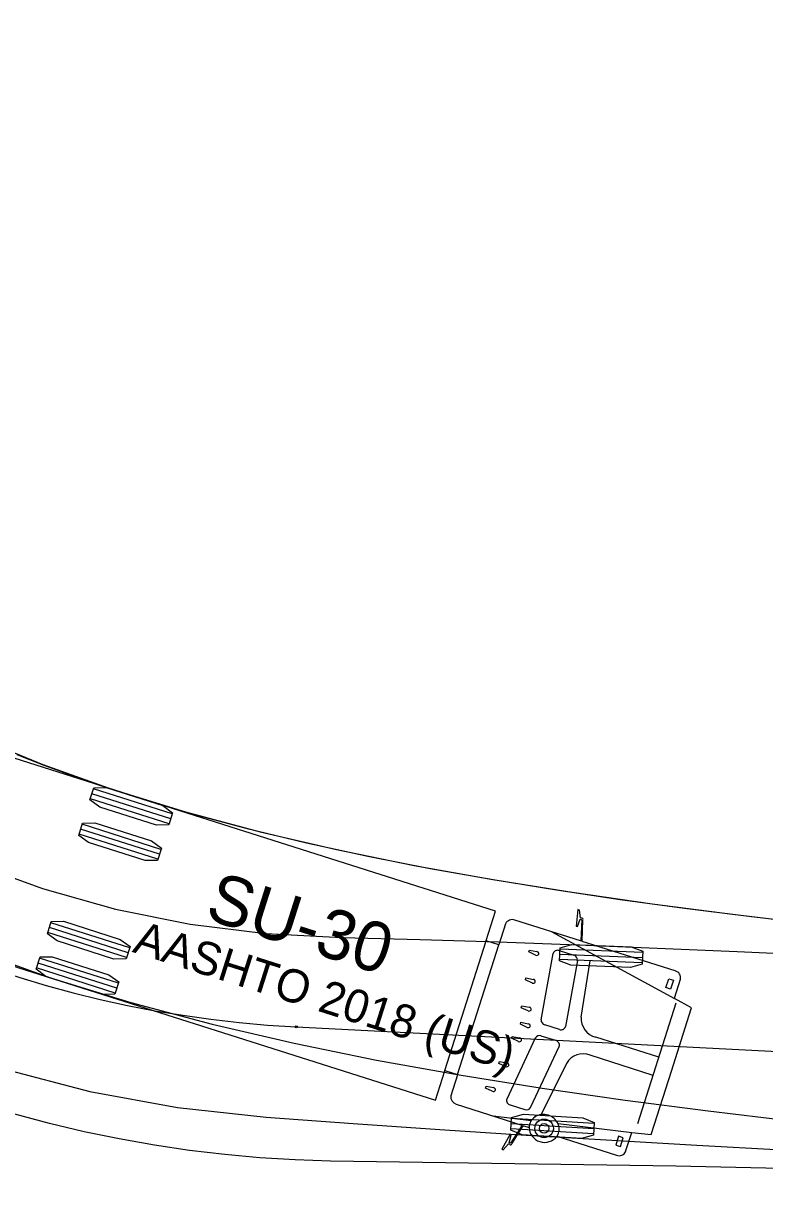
# Model space of a CAD drawing. Extents: x 260275 to 261282, y 610916 to 614143.
# Drawn here: x 261055.33 to 261085.23, y 611607.94 to 611654.93 of the extents above; entities that cross this region are included whole.
import ezdxf

# ---------------------------------------------------------------- set-up
doc = ezdxf.new("R2010")
doc.units = 0
doc.layers.add('UT_X_Water_Cells', color=7, linetype='Continuous')

msp = doc.modelspace()

# ---------------------------------------------------------------- linework, layer by layer
at = {"layer": 'UT_X_Water_Cells'}
for p, q in [((261061.276, 611622.828), (261058.1, 611623.838)), ((261061.339, 611623.027), (261058.163, 611624.037)), ((261061.213, 611622.63), (261058.036, 611623.64)), ((261060.885, 611621.597), (261057.708, 611622.607)), ((261060.758, 611621.2), (261057.582, 611622.21)), ((261060.821, 611621.399), (261057.645, 611622.409)), ((261059.496, 611617.229), (261056.319, 611618.24)), ((261059.559, 611617.428), (261056.382, 611618.438)), ((261059.622, 611617.626), (261056.445, 611618.637)), ((261076.646, 611618.273), (261081.591, 611615.583)), ((261072.337, 611612.669), (261074.002, 611617.903)), ((261072.844, 611612.508), (261074.508, 611617.741)), ((261075.719, 611617.457), (261075.744, 611617.535)), ((261075.994, 611617.331), (261075.719, 611617.457)), ((261075.744, 611617.535), (261076.04, 611617.479)), ((261076.219, 611614.725), (261076.7, 611617.399)), ((261076.948, 611617.511), (261077.535, 611617.324)), ((261080.303, 611617.224), (261076.972, 611617.358)), ((261080.311, 611617.432), (261076.981, 611617.567)), ((261059.041, 611615.8), (261055.864, 611616.81)), ((261059.104, 611615.998), (261055.928, 611617.009)), ((261059.167, 611616.197), (261055.991, 611617.207)), ((261080.295, 611617.016), (261076.964, 611617.15)), ((261077.682, 611617.118), (261077.201, 611614.444)), ((261077.834, 611614.832), (261078.192, 611617.094)), ((261075.581, 611616.328), (261075.606, 611616.407)), ((261075.869, 611616.2), (261075.581, 611616.328)), ((261075.606, 611616.407), (261075.916, 611616.347)), ((261081.251, 611616.017), (261081.365, 611616.378)), ((261081.365, 611616.378), (261081.55, 611616.319)), ((261081.436, 611615.958), (261081.251, 611616.017)), ((261081.55, 611616.319), (261081.436, 611615.958)), ((261080.115, 611610.538), (261081.663, 611615.403)), ((261075.416, 611615.208), (261075.441, 611615.287)), ((261075.691, 611615.083), (261075.416, 611615.208)), ((261075.441, 611615.287), (261075.738, 611615.23)), ((261075.38, 611614.539), (261075.405, 611614.618)), ((261075.655, 611614.414), (261075.38, 611614.539)), ((261075.405, 611614.618), (261075.701, 611614.561)), ((261076.953, 611614.332), (261076.365, 611614.519)), ((261066.343, 611614.434), (261269.731, 611604.069)), ((261075.983, 611613.982), (261074.831, 611611.521)), ((261075.023, 611613.973), (261075.048, 611614.051)), ((261075.298, 611613.848), (261075.023, 611613.973)), ((261075.048, 611614.051), (261075.345, 611613.995)), ((261076.809, 611613.879), (261076.221, 611614.066)), ((261080.965, 611613.208), (261078.422, 611614.017)), ((261075.795, 611611.183), (261076.946, 611613.644)), ((261074.511, 611612.963), (261074.536, 611613.042)), ((261074.536, 611613.042), (261074.832, 611612.985)), ((261080.733, 611612.479), (261078.19, 611613.287)), ((261074.786, 611612.838), (261074.511, 611612.963)), ((261077.24, 611612.961), (261076.219, 611610.898)), ((261073.972, 611611.962), (261073.997, 611612.041)), ((261074.246, 611611.837), (261073.972, 611611.962)), ((261073.997, 611612.041), (261074.293, 611611.984)), ((261074.969, 611611.287), (261075.556, 611611.1)), ((261074.282, 611610.84), (261075.82, 611610.658)), ((261078.353, 611610.53), (261075.025, 611610.733)), ((261078.327, 611610.114), (261075, 611610.317)), ((261078.34, 611610.322), (261075.013, 611610.525)), ((261076.898, 611610.53), (261079.872, 611610.179)), ((261076.857, 611610.02), (261079.261, 611609.256)), ((261079.344, 611610.021), (261079.229, 611609.66)), ((261079.529, 611609.962), (261079.344, 611610.021)), ((261079.414, 611609.601), (261079.529, 611609.962)), ((261079.229, 611609.66), (261079.414, 611609.601))]:
    msp.add_line(p, q, dxfattribs=at)
for points in [[(261053.428, 611626.129), (261056.118, 611625.015), (261058.944, 611624.011), (261061.876, 611623.111), (261064.891, 611622.308), (261067.97, 611621.591), (261071.1, 611620.951), (261074.269, 611620.378), (261077.468, 611619.864), (261080.693, 611619.4), (261083.936, 611618.979), (261087.195, 611618.596)], [(261074.781, 611618.598), (261074.509, 611617.744), (261074.505, 611617.743), (261074.003, 611617.902), (261074.005, 611617.913), (261074.382, 611619.098), (261054.096, 611625.549), (261052.884, 611621.737), (261051.672, 611617.925), (261071.957, 611611.474), (261072.334, 611612.658), (261072.338, 611612.669), (261072.84, 611612.509), (261072.843, 611612.505), (261072.571, 611611.651)], [(261055.07, 611625.429), (261056.161, 611624.999), (261057.273, 611624.586), (261058.405, 611624.191), (261059.555, 611623.813), (261061.903, 611623.104), (261064.305, 611622.456), (261066.75, 611621.864), (261069.232, 611621.323), (261071.743, 611620.829), (261074.279, 611620.377), (261076.835, 611619.961), (261079.407, 611619.579), (261081.994, 611619.226), (261084.592, 611618.899), (261087.2, 611618.596)], [(261053.21, 611621.06), (261056.099, 611620.012), (261059.056, 611619.184), (261062.066, 611618.578), (261065.112, 611618.198), (261068.183, 611618.045), (261071.333, 611617.966), (261074.504, 611617.865), (261077.694, 611617.746), (261080.902, 611617.614), (261084.127, 611617.473), (261087.366, 611617.325)], [(261077.847, 611618.814), (261077.802, 611618.829), (261077.801, 611618.829), (261077.765, 611619.15), (261077.703, 611619.17), (261077.703, 611619.167), (261077.637, 611618.5), (261077.637, 611618.497), (261077.69, 611618.48), (261077.691, 611618.482), (261077.795, 611618.782), (261077.796, 611618.782), (261077.838, 611618.768)], [(261077.854, 611618.751), (261077.854, 611618.751), (261077.815, 611617.906), (261077.802, 611617.905), (261075.159, 611618.746)], [(261081.625, 611616.689), (261077.877, 611617.881), (261077.867, 611617.891), (261077.904, 611618.752), (261077.904, 611618.753)], [(261053.236, 611617.552), (261056.422, 611616.419), (261059.665, 611615.423), (261062.948, 611614.548), (261066.256, 611613.777), (261069.582, 611613.096), (261072.918, 611612.493), (261076.261, 611611.956), (261079.606, 611611.474), (261082.953, 611611.04), (261086.299, 611610.647)], [(261079.627, 611609.406), (261079.871, 611610.175), (261079.877, 611610.178), (261080.657, 611610.086), (261080.672, 611610.126), (261081.473, 611612.645), (261082.274, 611615.164), (261082.285, 611615.205), (261081.595, 611615.58), (261081.592, 611615.586), (261081.837, 611616.356)], [(261054.534, 611612.738), (261058.013, 611611.83), (261061.551, 611611.18), (261065.122, 611610.792), (261068.642, 611610.531), (261072.138, 611610.292), (261075.613, 611610.071), (261079.067, 611609.863), (261082.504, 611609.665), (261085.925, 611609.474)], [(261072.795, 611611.312), (261075.438, 611610.472), (261075.448, 611610.463), (261074.992, 611609.751), (261074.991, 611609.751)], [(261087.099, 611608.697), (261081.645, 611608.809), (261067.722, 611609.015), (261066.3, 611609.063), (261064.878, 611609.151), (261063.456, 611609.28), (261062.036, 611609.449), (261060.618, 611609.659), (261059.203, 611609.911), (261057.792, 611610.204), (261056.385, 611610.538), (261054.985, 611610.914)], [(261075.031, 611609.72), (261075.032, 611609.721), (261075.499, 611610.445), (261075.513, 611610.448), (261075.73, 611610.379)], [(261074.969, 611609.746), (261074.926, 611609.759), (261074.926, 611609.76), (261075.014, 611610.065), (261075.015, 611610.067), (261074.962, 611610.084), (261074.96, 611610.082), (261074.628, 611609.499), (261074.627, 611609.496), (261074.689, 611609.476), (261074.904, 611609.718), (261074.904, 611609.718), (261074.95, 611609.704)]]:
    msp.add_lwpolyline(points, dxfattribs=at)
for points in [[(261061.355, 611623.076), (261061.197, 611622.58), (261060.705, 611622.572), (261058.418, 611623.3), (261058.021, 611623.591), (261058.178, 611624.086), (261058.67, 611624.094), (261060.958, 611623.367)], [(261060.9, 611621.646), (261060.743, 611621.151), (261060.25, 611621.143), (261057.963, 611621.87), (261057.566, 611622.161), (261057.724, 611622.657), (261058.216, 611622.664), (261060.503, 611621.937)], [(261059.638, 611617.676), (261059.48, 611617.18), (261058.988, 611617.172), (261056.701, 611617.9), (261056.303, 611618.19), (261056.461, 611618.686), (261056.953, 611618.694), (261059.24, 611617.966)], [(261080.314, 611617.484), (261080.293, 611616.964), (261079.82, 611616.827), (261077.422, 611616.923), (261076.962, 611617.099), (261076.983, 611617.618), (261077.455, 611617.756), (261079.854, 611617.659)], [(261059.183, 611616.246), (261059.025, 611615.751), (261058.533, 611615.743), (261056.246, 611616.47), (261055.849, 611616.761), (261056.006, 611617.256), (261056.499, 611617.264), (261058.786, 611616.537)], [(261078.356, 611610.582), (261078.324, 611610.063), (261077.849, 611609.935), (261075.453, 611610.081), (261074.997, 611610.265), (261075.028, 611610.784), (261075.504, 611610.912), (261077.899, 611610.767)]]:
    msp.add_lwpolyline(points, close=True, dxfattribs=at)
for centre, radius in [((261066.343, 611614.434), 0.0417), ((261066.343, 611614.434), 0.0417), ((261076.338, 611610.338), 0.374), ((261076.338, 611610.338), 0.193)]:
    msp.add_circle(centre, radius, dxfattribs=at)
for centre, radius, start, end in [((261068.634, 611659.376), 45, 177.1255, 267.0825), ((261052.872, 611624.635), 42, 177.1255, 293.7992), ((261075.061, 611618.438), 0.323, 72.3587, 150.2071), ((261077.876, 611618.788), 0.0434, 207.7724, 238.4451), ((261077.874, 611618.783), 0.0418, 314.8506, 131.8655), ((261076.038, 611617.411), 0.0909, 240.6395, 334.8747), ((261076.031, 611617.388), 0.091, 349.8782, 84.0421), ((261076.875, 611617.341), 0.184, 66.8948, 161.7661), ((261077.49, 611617.137), 0.193, 354.5011, 76.4156), ((261075.893, 611616.26), 0.091, 349.8782, 84.0421), ((261081.561, 611616.415), 0.282, 347.9071, 76.9865), ((261075.9, 611616.282), 0.0909, 240.6395, 334.8747), ((261075.735, 611615.162), 0.0909, 240.6395, 334.8747), ((261075.728, 611615.14), 0.091, 349.8782, 84.0421), ((261075.699, 611614.494), 0.091, 240.6752, 334.8391), ((261075.692, 611614.471), 0.091, 349.8782, 84.0421), ((261076.41, 611614.706), 0.193, 174.4961, 256.4205), ((261077.025, 611614.502), 0.184, 246.9004, 341.7605), ((261078.605, 611614.768), 0.773, 175.2491, 256.3333), ((261075.335, 611613.904), 0.0909, 349.8426, 84.0778), ((261076.15, 611613.887), 0.193, 68.2968, 150.2212), ((261075.342, 611613.927), 0.091, 240.6752, 334.8391), ((261076.77, 611613.699), 0.184, 342.9568, 77.8169), ((261077.905, 611612.569), 0.773, 68.384, 149.4682), ((261074.83, 611612.918), 0.091, 240.6752, 334.8391), ((261074.823, 611612.895), 0.0909, 349.8426, 84.0778), ((261072.893, 611611.62), 0.323, 174.5103, 252.3587), ((261074.291, 611611.917), 0.091, 240.6752, 334.8391), ((261074.284, 611611.894), 0.0909, 349.8426, 84.0778), ((261075.007, 611611.467), 0.184, 162.9512, 257.8225), ((261075.627, 611611.279), 0.193, 248.3018, 330.2162), ((261076.255, 611610.364), 0.524, 124.6177, 178.4178), ((261076.31, 611610.274), 0.63, 71.7135, 124.1163), ((261076.325, 611610.27), 0.629, 24.4042, 73.0935), ((261076.358, 611610.402), 0.628, 182.112, 322.6037), ((261076.42, 611610.312), 0.526, 326.3038, 24.5498), ((261074.988, 611609.708), 0.0434, 86.2722, 116.945), ((261074.99, 611609.713), 0.0418, 192.8518, 9.8667), ((261079.368, 611609.517), 0.282, 247.7308, 336.8103)]:
    msp.add_arc(centre, radius, start, end, dxfattribs=at)

# ---------------------------------------------------------------- texts
for s, height, p in [('SU-30', 2, (261062.598, 611618.815)), ('AASHTO 2018 (US)', 1.33333, (261059.695, 611617.465))]:
    msp.add_text(s, height=height, rotation=342.3587, dxfattribs=at).set_placement(p)

doc.saveas('drawing.dxf')
